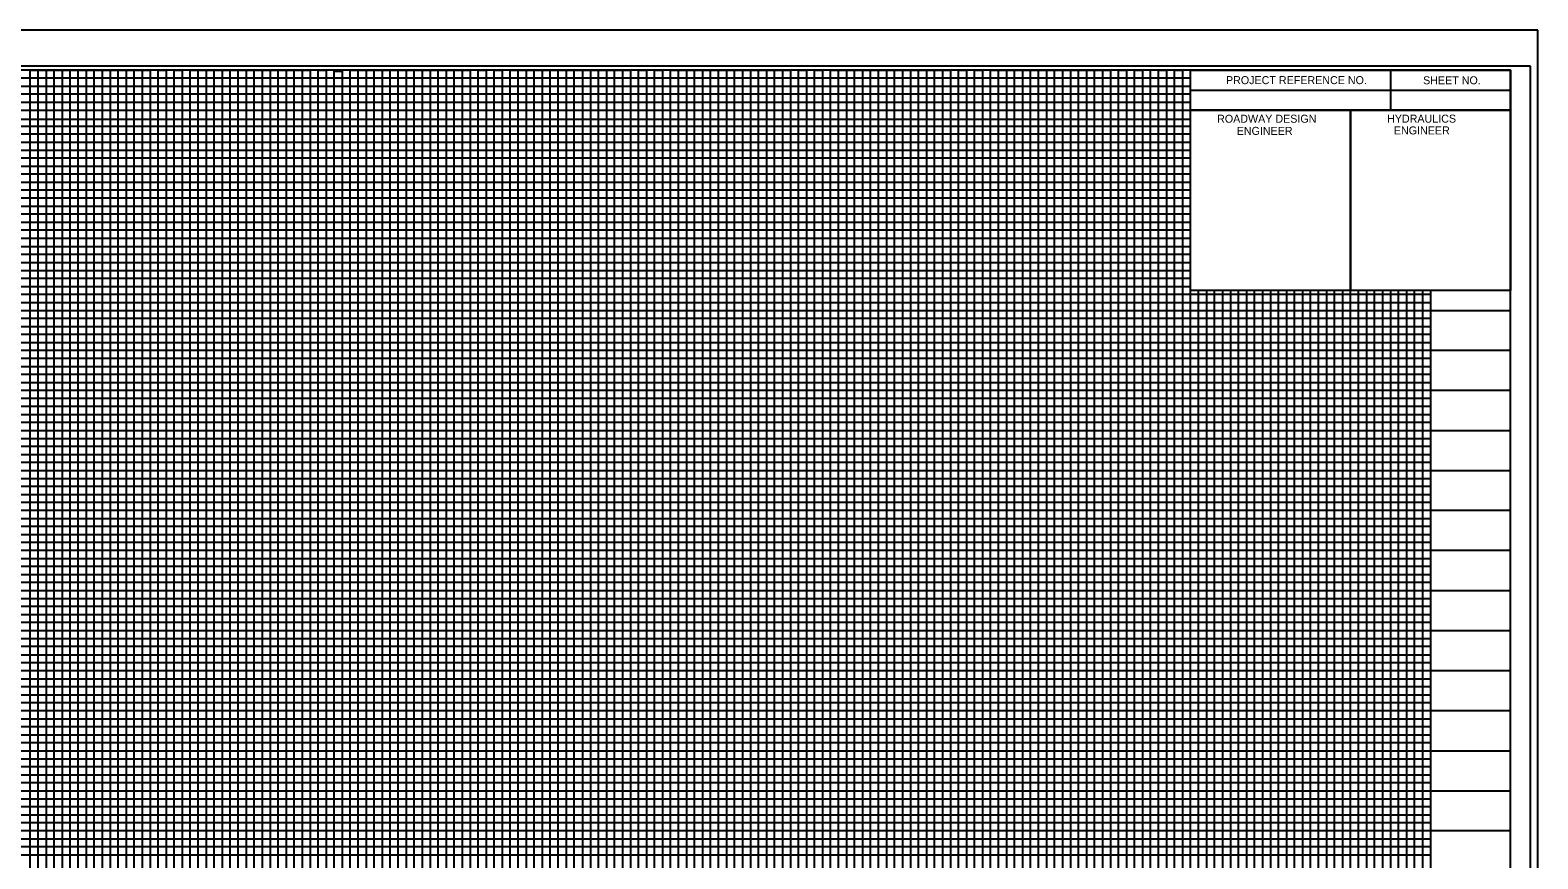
# Model space of a CAD drawing. Extents: x 2345490 to 2436403, y 465165 to 573888.
# Drawn here: x 2424020 to 2424962, y 523738 to 524256 of the extents above; entities that cross this region are included whole.
import ezdxf

# ---------------------------------------------------------------- set-up
doc = ezdxf.new("R2010")
doc.units = 0
for name, color, linetype in [('Old_Level_1', 7, 'Continuous'), ('Old_Level_18', 7, 'Continuous'), ('Old_Level_40', 7, 'Continuous'), ('Old_Level_41', 7, 'Continuous'), ('Old_Level_42', 7, 'Continuous'), ('Old_Level_43', 7, 'Continuous'), ('Old_Level_44', 7, 'Continuous'), ('Old_Level_50', 7, 'Continuous'), ('Old_Level_51', 7, 'Continuous'), ('Old_Level_52', 7, 'Continuous'), ('Old_Level_53', 7, 'Continuous')]:
    doc.layers.add(name, color=color, linetype=linetype)

msp = doc.modelspace()

# ---------------------------------------------------------------- linework, layer by layer
at = {"layer": 'Old_Level_1'}
msp.add_line((2424957.825, 524233.4995), (2424957.825, 524233.4995), dxfattribs=at)
at = {"layer": 'Old_Level_18'}
msp.add_lwpolyline([(2424945.325, 524230.9495), (2423445.325, 524230.9495), (2423445.325, 523180.9495), (2424945.325, 523180.9495)], close=True, dxfattribs=at)
at = {"layer": 'Old_Level_40'}
for p, q in [((2424870.325, 524230.8995), (2424870.325, 524205.8995)), ((2424745.275, 524218.3995), (2424945.325, 524218.3995)), ((2424845.325, 524205.8995), (2424845.325, 524093.4495))]:
    msp.add_line(p, q, dxfattribs=at)
for points in [[(2424745.275, 524230.9495), (2424945.325, 524230.9495), (2424945.325, 524205.8995), (2424745.275, 524205.8995)], [(2424745.275, 524205.8995), (2424845.325, 524205.8995), (2424845.325, 524093.3995), (2424745.275, 524093.3995)], [(2424845.325, 524205.8995), (2424945.325, 524205.8995), (2424945.325, 524093.3995), (2424845.325, 524093.3995)]]:
    msp.add_lwpolyline(points, close=True, dxfattribs=at)
at = {"layer": 'Old_Level_41'}
for points in [[(2424020.325, 523205.9495), (2424020.325, 524230.9495), (2424070.325, 524230.9495), (2424070.325, 523205.9495)], [(2424045.325, 523205.9495), (2424045.325, 524230.9495), (2424095.325, 524230.9495), (2424095.325, 523205.9495)], [(2424120.325, 523205.9495), (2424120.325, 524230.9495), (2424170.325, 524230.9495), (2424170.325, 523205.9495)], [(2424145.325, 523205.9495), (2424145.325, 524230.9495), (2424195.325, 524230.9495), (2424195.325, 523205.9495)], [(2424220.325, 523205.9495), (2424220.325, 524230.9495), (2424270.325, 524230.9495), (2424270.325, 523205.9495)], [(2424245.325, 523205.9495), (2424245.325, 524230.9495), (2424295.325, 524230.9495), (2424295.325, 523205.9495)], [(2424320.325, 523205.9495), (2424320.325, 524230.9495), (2424370.325, 524230.9495), (2424370.325, 523205.9495)], [(2424345.325, 523205.9495), (2424345.325, 524230.9495), (2424395.325, 524230.9495), (2424395.325, 523205.9495)], [(2424420.325, 523205.9495), (2424420.325, 524230.9495), (2424470.325, 524230.9495), (2424470.325, 523205.9495)], [(2424445.325, 523205.9495), (2424445.325, 524230.9495), (2424495.325, 524230.9495), (2424495.325, 523205.9495)], [(2424520.325, 523205.9495), (2424520.325, 524230.9495), (2424570.325, 524230.9495), (2424570.325, 523205.9495)], [(2424545.325, 523205.9495), (2424545.325, 524230.9495), (2424595.325, 524230.9495), (2424595.325, 523205.9495)], [(2424620.325, 523205.9495), (2424620.325, 524230.9495), (2424670.325, 524230.9495), (2424670.325, 523205.9495)], [(2424645.325, 523205.9495), (2424645.325, 524230.9495), (2424695.325, 524230.9495), (2424695.325, 523205.9495)], [(2424720.325, 523205.9495), (2424720.325, 524230.9495)], [(2424745.325, 523205.9495), (2424745.325, 524230.9495), (2424771.625, 524230.9495)], [(2423445.325, 524180.9495), (2424745.275, 524180.9495)], [(2424745.275, 524130.9495), (2423445.325, 524130.9495), (2423445.325, 524080.8995), (2424945.325, 524080.8995)], [(2424945.325, 524055.9495), (2423445.325, 524055.9495), (2423445.325, 524105.9495), (2424745.275, 524105.9495)], [(2424770.325, 524093.3995), (2424770.325, 523205.9495), (2424820.325, 523205.9495), (2424820.325, 524093.3995)], [(2424870.325, 524093.3995), (2424870.325, 523205.9495)], [(2424945.325, 524030.9495), (2423445.325, 524030.9495), (2423445.325, 523980.9495), (2424945.325, 523980.9495)], [(2424945.325, 523955.9495), (2423445.325, 523955.9495), (2423445.325, 524005.9495), (2424945.325, 524005.9495)], [(2424945.325, 523930.9495), (2423445.325, 523930.9495), (2423445.325, 523880.9495), (2424945.325, 523880.9495)], [(2424945.325, 523830.9495), (2423445.325, 523830.9495), (2423445.325, 523780.9495), (2424945.325, 523780.9495)]]:
    msp.add_lwpolyline(points, dxfattribs=at)
at = {"layer": 'Old_Level_42'}
for points in [[(2424745.275, 524155.9495), (2423445.425, 524155.9495), (2423445.425, 524205.8995), (2424745.275, 524205.8995)], [(2424795.325, 524093.3995), (2424795.325, 523205.9495), (2424845.325, 523205.9495), (2424845.325, 524093.3995)], [(2424895.325, 524093.3995), (2424895.325, 523205.9495), (2424945.325, 523205.9495)], [(2424945.325, 523855.9495), (2423445.325, 523855.9495), (2423445.325, 523905.9495), (2424945.325, 523905.9495)], [(2424945.325, 523755.9495), (2423445.325, 523755.9495), (2423445.325, 523805.9495), (2424945.325, 523805.9495)]]:
    msp.add_lwpolyline(points, dxfattribs=at)
at = {"layer": 'Old_Level_43'}
for p, q in [((2424895.325, 524050.9495), (2423495.325, 524050.9495)), ((2423495.325, 524045.9495), (2424895.325, 524045.9495)), ((2424895.325, 524025.9495), (2423495.325, 524025.9495))]:
    msp.add_line(p, q, dxfattribs=at)
for points in [[(2424745.275, 524225.9495), (2423495.325, 524225.9495), (2423495.325, 524220.9495), (2424745.275, 524220.9495)], [(2424025.325, 523205.9495), (2424025.325, 524230.9495), (2424030.325, 524230.9495), (2424030.325, 523205.9495)], [(2424035.325, 523205.9495), (2424035.325, 524230.9495), (2424040.325, 524230.9495), (2424040.325, 523205.9495)], [(2424050.325, 523205.9495), (2424050.325, 524230.9495), (2424055.325, 524230.9495), (2424055.325, 523205.9495)], [(2424060.325, 523205.9495), (2424060.325, 524230.9495), (2424065.325, 524230.9495), (2424065.325, 523205.9495)], [(2424075.325, 523205.9495), (2424075.325, 524230.9495), (2424080.325, 524230.9495), (2424080.325, 523205.9495)], [(2424085.325, 523205.9495), (2424085.325, 524230.9495), (2424090.325, 524230.9495), (2424090.325, 523205.9495)], [(2424100.325, 523205.9495), (2424100.325, 524230.9495), (2424105.325, 524230.9495), (2424105.325, 523205.9495)], [(2424110.325, 523205.9495), (2424110.325, 524230.9495), (2424115.325, 524230.9495), (2424115.325, 523205.9495)], [(2424125.325, 523205.9495), (2424125.325, 524230.9495), (2424130.325, 524230.9495), (2424130.325, 523205.9495)], [(2424135.325, 523205.9495), (2424135.325, 524230.9495), (2424140.325, 524230.9495), (2424140.325, 523205.9495)], [(2424150.325, 523205.9495), (2424150.325, 524230.9495), (2424155.325, 524230.9495), (2424155.325, 523205.9495)], [(2424160.325, 523205.9495), (2424160.325, 524230.9495), (2424165.325, 524230.9495), (2424165.325, 523205.9495)], [(2424175.325, 523205.9495), (2424175.325, 524230.9495), (2424180.325, 524230.9495), (2424180.325, 523205.9495)], [(2424185.325, 523205.9495), (2424185.325, 524230.9495), (2424190.325, 524230.9495), (2424190.325, 523205.9495)], [(2424200.325, 523205.9495), (2424200.325, 524230.9495), (2424205.325, 524230.9495), (2424205.325, 523205.9495)], [(2424210.325, 523205.9495), (2424210.325, 524230.3495), (2424215.325, 524230.3495), (2424215.325, 523205.9495)], [(2424225.325, 523205.9495), (2424225.325, 524230.9495), (2424230.325, 524230.9495), (2424230.325, 523205.9495)], [(2424235.325, 523205.9495), (2424235.325, 524230.9495), (2424240.325, 524230.9495), (2424240.325, 523205.9495)], [(2424250.325, 523205.9495), (2424250.325, 524230.9495), (2424255.325, 524230.9495), (2424255.325, 523205.9495)], [(2424260.325, 523205.9495), (2424260.325, 524230.9495), (2424265.325, 524230.9495), (2424265.325, 523205.9495)], [(2424275.325, 523205.9495), (2424275.325, 524230.9495), (2424280.325, 524230.9495), (2424280.325, 523205.9495)], [(2424285.325, 523205.9495), (2424285.325, 524230.9495), (2424290.325, 524230.9495), (2424290.325, 523205.9495)], [(2424300.325, 523205.9495), (2424300.325, 524230.9495), (2424305.325, 524230.9495), (2424305.325, 523205.9495)], [(2424310.325, 523205.9495), (2424310.325, 524230.9495), (2424315.325, 524230.9495), (2424315.325, 523205.9495)], [(2424325.325, 523205.9495), (2424325.325, 524230.9495), (2424330.325, 524230.9495), (2424330.325, 523205.9495)], [(2424335.325, 523205.9495), (2424335.325, 524230.9495), (2424340.325, 524230.9495), (2424340.325, 523205.9495)], [(2424350.325, 523205.9495), (2424350.325, 524230.9495), (2424355.325, 524230.9495), (2424355.325, 523205.9495)], [(2424360.325, 523205.9495), (2424360.325, 524230.9495), (2424365.325, 524230.9495), (2424365.325, 523205.9495)], [(2424375.325, 523205.9495), (2424375.325, 524230.9495), (2424380.325, 524230.9495), (2424380.325, 523205.9495)], [(2424385.325, 523205.9495), (2424385.325, 524230.9495), (2424390.325, 524230.9495), (2424390.325, 523205.9495)], [(2424400.325, 523205.9495), (2424400.325, 524230.9495), (2424405.325, 524230.9495), (2424405.325, 523205.9495)], [(2424410.325, 523205.9495), (2424410.325, 524230.9495), (2424415.325, 524230.9495), (2424415.325, 523205.9495)], [(2424425.325, 523205.9495), (2424425.325, 524230.9495), (2424430.325, 524230.9495), (2424430.325, 523205.9495)], [(2424435.325, 523205.9495), (2424435.325, 524230.9495), (2424440.325, 524230.9495), (2424440.325, 523205.9495)], [(2424450.325, 523205.9495), (2424450.325, 524230.9495), (2424455.325, 524230.9495), (2424455.325, 523205.9495)], [(2424460.325, 523205.9495), (2424460.325, 524230.9495), (2424465.325, 524230.9495), (2424465.325, 523205.9495)], [(2424475.325, 523205.9495), (2424475.325, 524230.9495), (2424480.325, 524230.9495), (2424480.325, 523205.9495)], [(2424485.325, 523205.9495), (2424485.325, 524230.9495), (2424490.325, 524230.9495), (2424490.325, 523205.9495)], [(2424500.325, 523205.9495), (2424500.325, 524230.9495), (2424505.325, 524230.9495), (2424505.325, 523205.9495)], [(2424510.325, 523205.9495), (2424510.325, 524230.9495), (2424515.325, 524230.9495), (2424515.325, 523205.9495)], [(2424525.325, 523205.9495), (2424525.325, 524230.9495), (2424530.325, 524230.9495), (2424530.325, 523205.9495)], [(2424535.325, 523205.9495), (2424535.325, 524230.9495), (2424540.325, 524230.9495), (2424540.325, 523205.9495)], [(2424550.325, 523205.9495), (2424550.325, 524230.9495), (2424555.325, 524230.9495), (2424555.325, 523205.9495)], [(2424560.325, 523205.9495), (2424560.325, 524230.9495), (2424565.325, 524230.9495), (2424565.325, 523205.9495)], [(2424575.325, 523205.9495), (2424575.325, 524230.9495), (2424580.325, 524230.9495), (2424580.325, 523205.9495)], [(2424585.325, 523205.9495), (2424585.325, 524230.9495), (2424590.325, 524230.9495), (2424590.325, 523205.9495)], [(2424600.325, 523205.9495), (2424600.325, 524230.9495), (2424605.325, 524230.9495), (2424605.325, 523205.9495)], [(2424610.325, 523205.9495), (2424610.325, 524230.9495), (2424615.325, 524230.9495), (2424615.325, 523205.9495)], [(2424625.325, 523205.9495), (2424625.325, 524230.9495), (2424630.325, 524230.9495), (2424630.325, 523205.9495)], [(2424635.325, 523205.9495), (2424635.325, 524230.9495), (2424640.325, 524230.9495), (2424640.325, 523205.9495)], [(2424650.325, 523205.9495), (2424650.325, 524230.9495), (2424655.325, 524230.9495), (2424655.325, 523205.9495)], [(2424660.325, 523205.9495), (2424660.325, 524230.9495), (2424665.325, 524230.9495), (2424665.325, 523205.9495)], [(2424675.325, 523205.9495), (2424675.325, 524230.9495), (2424680.325, 524230.9495), (2424680.325, 523205.9495)], [(2424685.325, 523205.9495), (2424685.325, 524230.9495), (2424690.325, 524230.9495), (2424690.325, 523205.9495)], [(2424700.325, 523205.9495), (2424700.325, 524230.9495), (2424705.325, 524230.9495), (2424705.325, 523205.9495)], [(2424710.325, 523205.9495), (2424710.325, 524230.9495), (2424715.325, 524230.9495), (2424715.325, 523205.9495)], [(2424725.325, 523205.9495), (2424725.325, 524230.9495), (2424730.325, 524230.9495), (2424730.325, 523205.9495)], [(2424735.325, 523205.9495), (2424735.325, 524230.9495), (2424740.325, 524230.9495), (2424740.325, 523205.9495)], [(2424745.275, 524215.9495), (2423495.325, 524215.9495), (2423495.325, 524210.9495), (2424745.275, 524210.9495)], [(2424745.275, 524200.1995), (2423496.325, 524200.1995), (2423496.325, 524195.9495), (2424745.275, 524195.9495)], [(2424745.275, 524190.9495), (2423495.325, 524190.9495), (2423495.325, 524185.9495), (2424745.275, 524185.9495)], [(2424745.275, 524175.9495), (2423495.325, 524175.9495), (2423495.325, 524170.9495), (2424745.275, 524170.9495)], [(2424745.275, 524165.9495), (2423495.325, 524165.9495), (2423495.325, 524160.9495), (2424745.275, 524160.9495)], [(2424745.275, 524150.9495), (2423495.325, 524150.9495), (2423495.325, 524145.9495), (2424745.275, 524145.9495)], [(2424745.275, 524140.9495), (2423495.325, 524140.9495), (2423495.325, 524135.9495), (2424745.275, 524135.9495)], [(2424745.275, 524125.9495), (2423495.325, 524125.9495), (2423495.325, 524120.9495), (2424745.275, 524120.9495)], [(2424745.275, 524115.9495), (2423495.325, 524115.9495), (2423495.325, 524110.9495), (2424745.275, 524110.9495)], [(2424745.275, 524100.9495), (2423495.325, 524100.9495), (2423495.325, 524095.9495), (2424745.275, 524095.9495)], [(2424750.325, 523205.9495), (2424750.325, 524093.3995)], [(2424755.325, 524093.3995), (2424755.325, 523205.9495), (2424760.325, 523205.9495), (2424760.325, 524093.3995)], [(2424765.325, 524093.3995), (2424765.325, 523205.9495), (2424775.325, 523205.9495), (2424775.325, 524093.3995)], [(2424780.325, 524093.3995), (2424780.325, 523205.9495), (2424785.325, 523205.9495), (2424785.325, 524093.3995)], [(2424790.325, 524093.3995), (2424790.325, 523205.9495), (2424800.325, 523205.9495), (2424800.325, 524093.3995)], [(2424805.325, 524093.3995), (2424805.325, 523205.9495), (2424810.325, 523205.9495), (2424810.325, 524093.3995)], [(2424815.325, 524093.3995), (2424815.325, 523205.9495), (2424825.325, 523205.9495), (2424825.325, 524093.3995)], [(2424830.325, 524093.3995), (2424830.325, 523205.9495)], [(2424830.325, 523205.9495), (2424835.325, 523205.9495), (2424835.325, 524093.3995)], [(2424840.325, 524093.3995), (2424840.325, 523205.9495), (2424850.325, 523205.9495), (2424850.325, 524093.3995)], [(2424855.325, 524093.3995), (2424855.325, 523205.9495), (2424860.325, 523205.9495), (2424860.325, 524093.3995)], [(2424865.325, 524093.3995), (2424865.325, 523205.9495), (2424875.325, 523205.9495), (2424875.325, 524093.3995)], [(2424880.325, 524093.3995), (2424880.325, 523205.9495), (2424885.325, 523205.9495), (2424885.325, 524093.3995)], [(2424890.325, 524093.3995), (2424890.325, 523205.9495), (2424900.325, 523205.9495)], [(2424895.325, 524090.9495), (2423495.325, 524090.9495), (2423495.325, 524090.9495), (2423495.325, 524070.9495), (2424895.325, 524070.9495)], [(2423495.325, 524085.9495), (2424895.325, 524085.9495)], [(2424895.325, 524075.9495), (2423495.325, 524075.9495)], [(2424895.325, 524065.9495), (2423495.325, 524065.9495), (2423495.325, 524060.9495), (2424895.325, 524060.9495)], [(2424895.325, 524040.9495), (2423495.325, 524040.9495), (2423495.325, 524035.9495), (2424895.325, 524035.9495)], [(2424895.325, 524020.9495), (2423495.325, 524020.9495), (2423495.325, 524015.9495), (2424895.325, 524015.9495)], [(2424895.325, 524010.9495), (2423495.325, 524010.9495)], [(2423495.325, 524000.9495), (2424895.325, 524000.9495)], [(2424895.325, 523995.9495), (2423495.325, 523995.9495), (2423495.325, 523990.9495), (2424895.325, 523990.9495)], [(2424895.325, 523985.9495), (2423495.325, 523985.9495), (2423495.325, 523975.9495), (2424895.325, 523975.9495)], [(2424895.325, 523970.9495), (2423495.325, 523970.9495), (2423495.325, 523965.9495), (2424895.325, 523965.9495)], [(2424895.325, 523960.9495), (2423495.325, 523960.9495), (2423495.325, 523950.9495), (2424895.325, 523950.9495)], [(2424895.325, 523945.9495), (2423495.325, 523945.9495), (2423495.325, 523940.9495), (2424895.325, 523940.9495)], [(2424895.325, 523935.9495), (2423495.325, 523935.9495), (2423495.325, 523925.9495), (2424895.325, 523925.9495)], [(2424895.325, 523920.9495), (2423495.325, 523920.9495), (2423495.325, 523915.9495), (2424895.325, 523915.9495)], [(2424895.325, 523910.9495), (2423495.325, 523910.9495), (2423495.325, 523900.9495), (2424895.325, 523900.9495)], [(2424895.325, 523895.9495), (2423495.325, 523895.9495), (2423495.325, 523890.9495), (2424895.325, 523890.9495)], [(2424895.325, 523885.9495), (2423495.325, 523885.9495), (2423495.325, 523875.9495), (2424895.325, 523875.9495)], [(2424895.325, 523870.9495), (2423495.325, 523870.9495), (2423495.325, 523865.9495), (2424895.325, 523865.9495)], [(2424895.325, 523860.9495), (2423495.325, 523860.9495), (2423495.325, 523850.9495), (2424895.325, 523850.9495)], [(2424895.325, 523845.9495), (2423495.325, 523845.9495), (2423495.325, 523840.9495), (2424895.325, 523840.9495)], [(2424895.325, 523835.9495), (2423495.325, 523835.9495), (2423495.325, 523825.9495), (2424895.325, 523825.9495)], [(2424895.325, 523820.9495), (2423495.325, 523820.9495), (2423495.325, 523815.9495), (2424895.325, 523815.9495)], [(2424895.325, 523810.9495), (2423495.325, 523810.9495), (2423495.325, 523800.9495), (2424895.325, 523800.9495)], [(2424895.325, 523795.9495), (2423495.325, 523795.9495), (2423495.325, 523790.9495), (2424895.325, 523790.9495)], [(2424895.325, 523785.9495), (2423495.325, 523785.9495), (2423495.325, 523775.9495), (2424895.325, 523775.9495)], [(2424895.325, 523770.9495), (2423495.325, 523770.9495), (2423495.325, 523765.9495), (2424895.325, 523765.9495)], [(2424895.325, 523760.9495), (2423495.325, 523760.9495), (2423495.325, 523750.9495), (2424895.325, 523750.9495)], [(2424895.325, 523745.9495), (2423495.325, 523745.9495), (2423495.325, 523740.9495), (2424895.325, 523740.9495)]]:
    msp.add_lwpolyline(points, dxfattribs=at)
at = {"layer": 'Old_Level_50'}
msp.add_line((2424962.325, 524255.9495), (2424962.325, 524255.9495), dxfattribs=at)
msp.add_lwpolyline([(2424957.825, 524233.4995), (2423291.325, 524233.4995), (2423291.325, 523178.3995), (2424957.825, 523178.3995)], close=True, dxfattribs=at)
at = {"layer": 'Old_Level_51'}
msp.add_lwpolyline([(2424962.325, 524255.9495), (2423278.325, 524255.9495), (2423278.325, 523155.9495), (2424962.325, 523155.9495)], close=True, dxfattribs=at)
at = {"layer": 'Old_Level_52'}
msp.add_line((2424957.825, 524233.4995), (2424957.825, 524233.4995), dxfattribs=at)
at = {"layer": 'Old_Level_53'}
msp.add_line((2424957.825, 524233.4995), (2424957.825, 524233.4995), dxfattribs=at)

# ---------------------------------------------------------------- texts
at = {"layer": 'Old_Level_44'}
for s, p in [('PROJECT REFERENCE NO.', (2424767.475, 524222.2495)), ('SHEET NO.', (2424890.625, 524222.1495)), ('ROADWAY DESIGN', (2424761.925, 524198.1495)), ('ENGINEER', (2424774.175, 524190.5495)), ('HYDRAULICS', (2424868.125, 524198.1995)), ('ENGINEER', (2424872.375, 524190.8495))]:
    msp.add_text(s, height=5.0001, dxfattribs=at).set_placement(p)

doc.saveas('drawing.dxf')
